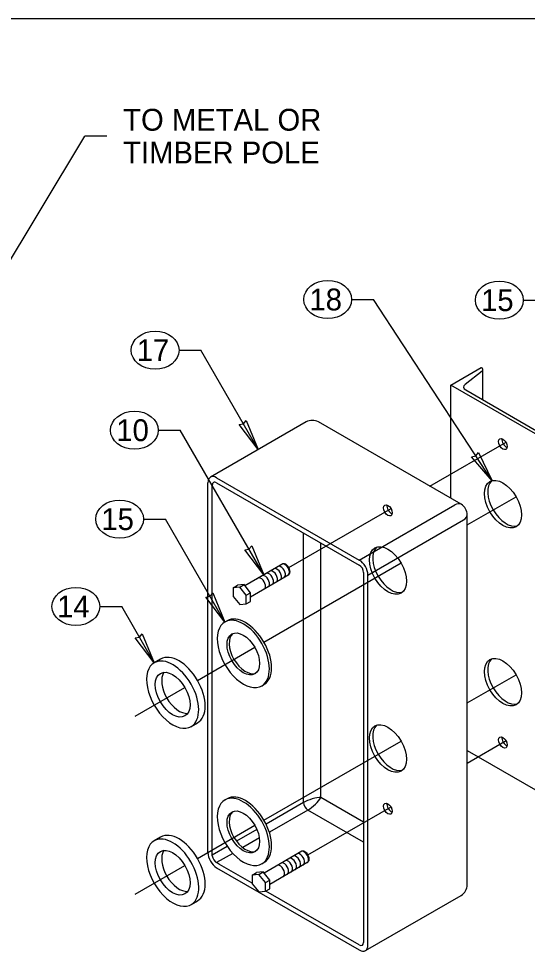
# Model space of a CAD drawing. Extents: x 99862 to 104211, y 98939 to 102076.
# Drawn here: x 101922 to 102294, y 101389 to 102076 of the extents above; entities that cross this region are included whole.
import ezdxf

# ---------------------------------------------------------------- set-up
doc = ezdxf.new("R2010")
doc.units = 0
for name, color, linetype in [('Level 1', 7, 'Continuous'), ('Level 13', 7, 'Continuous'), ('Level 14', 7, 'Continuous'), ('Level 15', 7, 'Continuous'), ('Level 17', 7, 'Continuous'), ('Level 19', 7, 'Continuous'), ('Level 20', 7, 'Continuous'), ('Level 37', 7, 'Continuous')]:
    doc.layers.add(name, color=color, linetype=linetype)

msp = doc.modelspace()

# ---------------------------------------------------------------- linework, layer by layer
at = {"layer": 'Level 1'}
msp.add_lwpolyline([(99862, 99999.5), (103151, 99999.5), (103151, 102075.5), (99862, 102075.5)], close=True, dxfattribs=at)
for centre in [(102116.86, 101671.77), (102105.16, 101665.01), (102108.08, 101666.7), (102111.01, 101668.39), (102113.93, 101670.08), (102099.31, 101661.64), (102102.23, 101663.33), (102127.93, 101459.54), (102130.85, 101461.23), (102113.31, 101451.1), (102116.23, 101452.79), (102119.15, 101454.48), (102122.08, 101456.17), (102125, 101457.85)]:
    msp.add_ellipse(centre, major_axis=(-2.33, 4.04), ratio=0.57735, start_param=2.878526, end_param=6.548134, dxfattribs=at)
at = {"layer": 'Level 13'}
for p, q in [((102132.38, 101780.05), (102062.38, 101739.63)), ((102245.77, 101719.78), (102141.38, 101780.05)), ((102066.88, 101739.19), (102171.27, 101678.92)), ((102060.52, 101467.64), (102060.52, 101735.51)), ((102063.7, 101462.25), (102063.7, 101733.68)), ((102066.88, 101735.51), (102171.27, 101675.25)), ((102171.27, 101678.92), (102241.27, 101719.34)), ((102250.27, 101440.99), (102250.27, 101711.99)), ((102177.63, 101667.9), (102247.63, 101708.31)), ((102130.52, 101501.26), (102130.52, 101698.77)), ((102143.25, 101504.94), (102143.25, 101691.42)), ((102174.45, 101669.73), (102174.45, 101398.74)), ((102177.63, 101396.9), (102177.63, 101667.9)), ((102174.45, 101486.92), (102143.25, 101504.93)), ((102130.52, 101501.26), (102103.08, 101485.42)), ((102133.7, 101495.75), (102105.46, 101479.44)), ((102174.45, 101472.22), (102133.7, 101495.75)), ((102096.36, 101481.54), (102081.42, 101472.91)), ((102098.17, 101475.24), (102085.97, 101468.19)), ((102060.52, 101464.52), (102060.52, 101467.64)), ((102074.7, 101469.03), (102063.7, 101462.68)), ((102078.68, 101463.98), (102066.88, 101457.17)), ((102069.03, 101455.93), (102066.88, 101457.17)), ((102092.99, 101442.09), (102069.03, 101455.93)), ((102066.88, 101453.49), (102171.27, 101393.23)), ((102171.27, 101396.9), (102102.88, 101436.38)), ((102175.77, 101392.78), (102245.77, 101433.2))]:
    msp.add_line(p, q, dxfattribs=at)
for centre, start, end in [((102136.88, 101772.26), 60, 120), ((102241.27, 101711.99), 360, 60), ((102241.27, 101440.99), 300, 360)]:
    msp.add_arc(centre, 9, start, end, dxfattribs=at)
for centre, major_axis, ratio, start_param, end_param in [((102066.88, 101731.84), (4.5, -7.79), 0.57735, 2.356194, 3.926991), ((102066.88, 101731.84), (2.25, -3.9), 0.57735, 2.356194, 3.926991), ((102194.65, 101716.68), (-2.25, 3.9), 0.57735, 0.55899, 2.582603), ((102241.27, 101711.99), (-4.5, -7.79), 0.57735, 3.141593, 3.926991), ((102241.27, 101711.99), (-9, 0), 0.57735, 2.356194, 3.141593), ((102194.65, 101672.58), (-9.56, 16.56), 0.57735, 0.12511, 3.016483), ((102171.27, 101671.57), (4.5, -7.79), 0.57735, 0.785398, 2.356194), ((102171.27, 101671.57), (2.25, -3.9), 0.57735, 0.785398, 2.356194), ((102194.65, 101542.15), (-9.56, 16.56), 0.57735, 0.12511, 3.016483), ((102136.88, 101501.26), (-8.97, -2.8), 0.264784, 3.844416, 5.415213), ((102136.88, 101501.26), (-6.91, -6.37), 0.264784, 0.867973, 2.438769), ((102133.7, 101499.42), (-2.25, 3.9), 0.57735, 0.785398, 2.356194), ((102194.65, 101498.06), (-2.25, 3.9), 0.57735, 0.55899, 2.582603), ((102066.88, 101460.84), (4.5, -7.79), 0.57735, 3.926991, 5.497787), ((102066.88, 101460.84), (2.25, -3.9), 0.57735, 4.04043, 5.497787), ((102171.27, 101400.57), (2.25, -3.9), 0.57735, 5.497787, 7.068583), ((102171.27, 101400.57), (4.5, -7.79), 0.57735, 5.497787, 7.068583)]:
    msp.add_ellipse(centre, major_axis=major_axis, ratio=ratio, start_param=start_param, end_param=end_param, dxfattribs=at)
for centre, major_axis in [((102192.26, 101715.3), (2.25, -3.9)), ((102192.26, 101671.21), (9.56, -16.56)), ((102192.26, 101540.77), (9.56, -16.56)), ((102192.26, 101496.68), (2.25, -3.9))]:
    msp.add_ellipse(centre, major_axis=major_axis, ratio=0.57735, dxfattribs=at)
at = {"layer": 'Level 14'}
for p, q in [((102025.89, 101606.33), (102021.2, 101603.63)), ((102048.2, 101556.86), (102052.89, 101559.57)), ((102025.89, 101475.9), (102021.2, 101473.19)), ((102048.2, 101426.43), (102052.89, 101429.13))]:
    msp.add_line(p, q, dxfattribs=at)
for centre, major_axis, start_param, end_param in [((102034.7, 101580.25), (-13.5, 23.38), 3.160814, 6.257875), ((102039.39, 101582.95), (-13.5, 23.38), 3.141593, 6.283185), ((102034.7, 101580.25), (-13.5, 23.38), 6.257875, 9.443999), ((102039.39, 101582.95), (9, -15.59), 3.404941, 4.712384), ((102039.39, 101582.95), (9, -15.59), 4.712384, 6.019837), ((102034.7, 101449.81), (-13.5, 23.38), 3.18937, 6.257397), ((102039.39, 101452.52), (-13.5, 23.38), 3.141593, 6.283185), ((102034.7, 101449.81), (-13.5, 23.38), 6.257397, 9.471744), ((102039.39, 101452.52), (9, -15.59), 3.404941, 4.712389), ((102039.39, 101452.52), (9, -15.59), 4.712389, 6.019837), ((102034.7, 101449.81), (-13.5, 23.38), 3.188559, 3.18937)]:
    msp.add_ellipse(centre, major_axis=major_axis, ratio=0.57735, start_param=start_param, end_param=end_param, dxfattribs=at)
for centre in [(102034.7, 101580.25), (102034.7, 101449.81)]:
    msp.add_ellipse(centre, major_axis=(9, -15.59), ratio=0.57735, dxfattribs=at)
at = {"layer": 'Level 15'}
for p, q in [((101891.9, 101858.89), (101970.48, 101989.49)), ((101986.48, 101989.49), (101970.48, 101989.49)), ((102165.69, 101869.79), (102181.69, 101869.79)), ((102268.46, 101737.02), (102181.69, 101869.79)), ((102291.28, 101869.3), (102307.28, 101869.3)), ((102039.35, 101832.65), (102055.35, 101832.65)), ((102097.38, 101759.84), (102055.35, 101832.65)), ((102024.22, 101774.02), (102040.22, 101774.02)), ((102101.4, 101668.04), (102040.22, 101774.02)), ((102222.9, 101732.99), (102278.67, 101765.19)), ((102250.27, 101704.7), (102285.99, 101725.32)), ((102119.72, 101673.42), (102194.51, 101716.6)), ((102013.39, 101708.87), (102029.39, 101708.87)), ((102072.92, 101633.48), (102029.39, 101708.87)), ((102101.51, 101618.81), (102201.82, 101676.73)), ((101981.39, 101644.87), (101997.39, 101644.87)), ((102021.2, 101603.63), (101997.39, 101644.87)), ((102052.89, 101590.74), (102094.86, 101614.97)), ((102250.27, 101574.27), (102285.99, 101594.89)), ((102007.35, 101564.45), (102043.7, 101585.44)), ((102101.51, 101488.38), (102201.82, 101546.29)), ((102250.27, 101530.17), (102278.67, 101546.57)), ((102133.71, 101462.88), (102194.51, 101497.98)), ((102052.89, 101460.31), (102094.86, 101484.54)), ((102007.35, 101434.01), (102043.7, 101455.01))]:
    msp.add_line(p, q, dxfattribs=at)
for points in [[(102097.38, 101759.84), (102083.38, 101778.12), (102086.5, 101778.7), (102088.55, 101781.11)], [(102268.46, 101737.02), (102253.47, 101754.5), (102256.55, 101755.24), (102258.47, 101757.76)], [(102101.4, 101668.04), (102087.41, 101686.32), (102090.52, 101686.9), (102092.57, 101689.3)], [(102072.92, 101633.48), (102058.92, 101651.76), (102062.03, 101652.34), (102064.09, 101654.75)], [(102021.2, 101603.63), (102007.2, 101621.91), (102010.32, 101622.48), (102012.37, 101624.89)]]:
    msp.add_lwpolyline(points, close=True, dxfattribs=at)
at = {"layer": 'Level 17'}
for p, q in [((102074.51, 101634.4), (102072.92, 101633.48)), ((102099.92, 101586.72), (102101.51, 101587.64)), ((102074.51, 101503.97), (102072.92, 101503.05)), ((102099.92, 101456.28), (102101.51, 101457.2))]:
    msp.add_line(p, q, dxfattribs=at)
for centre, major_axis, start_param, end_param in [((102086.42, 101610.1), (-13.5, 23.38), 3.156212, 6.257612), ((102088.01, 101611.02), (-13.5, 23.38), 3.141593, 6.283185), ((102086.42, 101610.1), (-13.5, 23.38), 6.263256, 9.438373), ((102088.01, 101611.02), (8.44, -14.61), 3.236014, 4.71245), ((102088.01, 101611.02), (8.44, -14.61), 4.71245, 6.188764), ((102086.42, 101479.67), (-13.5, 23.38), 3.161333, 6.262315), ((102088.01, 101480.59), (-13.5, 23.38), 3.141593, 6.283185), ((102086.42, 101479.67), (-13.5, 23.38), 6.262315, 9.444518), ((102088.01, 101480.59), (8.44, -14.61), 3.236014, 4.712389), ((102088.01, 101480.59), (8.44, -14.61), 4.712389, 6.188764)]:
    msp.add_ellipse(centre, major_axis=major_axis, ratio=0.57735, start_param=start_param, end_param=end_param, dxfattribs=at)
for centre in [(102086.42, 101610.1), (102086.42, 101479.67)]:
    msp.add_ellipse(centre, major_axis=(8.44, -14.61), ratio=0.57735, dxfattribs=at)
at = {"layer": 'Level 19'}
for p, q in [((102238.24, 101807.06), (102260.51, 101819.92)), ((102238.24, 101724.13), (102238.24, 101807.06)), ((102314.61, 101762.97), (102238.24, 101807.06)), ((102250.27, 101539.25), (102314.61, 101502.1))]:
    msp.add_line(p, q, dxfattribs=at)
for centre, major_axis in [((102276.42, 101763.89), (2.25, -3.9)), ((102276.42, 101719.8), (9.56, -16.56)), ((102276.42, 101589.37), (9.56, -16.56)), ((102276.42, 101545.27), (2.25, -3.9))]:
    msp.add_ellipse(centre, major_axis=major_axis, ratio=0.57735, dxfattribs=at)
at = {"layer": 'Level 20'}
for p, q in [((102260.51, 101819.92), (102260.82, 101819.74)), ((102261.14, 101817.2), (102248.67, 101807.58)), ((102261.81, 101796.21), (102261.81, 101818.37)), ((102249.17, 101803.51), (102308.45, 101769.28))]:
    msp.add_line(p, q, dxfattribs=at)
for centre in [(102148.19, 101869.79), (102273.78, 101869.3), (102021.85, 101832.65), (102006.72, 101774.02), (101995.89, 101708.87), (101963.89, 101644.87)]:
    msp.add_ellipse(centre, major_axis=(-17.5, 0), ratio=0.8, dxfattribs=at)
for centre, major_axis, start_param, end_param in [((102258.44, 101818.37), (3.38, 0), 5.640349, 7.068583), ((102252.99, 101805.71), (-5.4, 0), 5.640349, 7.068583), ((102278.81, 101765.27), (-2.25, 3.9), 0.55899, 2.582603), ((102278.81, 101721.18), (-9.56, 16.56), 0.12511, 3.016483), ((102278.81, 101590.74), (-9.56, 16.56), 0.12511, 3.016483), ((102278.81, 101546.65), (-2.25, 3.9), 0.55899, 2.582603)]:
    msp.add_ellipse(centre, major_axis=major_axis, ratio=0.57735, start_param=start_param, end_param=end_param, dxfattribs=at)
at = {"layer": 'Level 37'}
for p, q in [((102115.22, 101676.01), (102087.59, 101660.07)), ((102091.72, 101652.06), (102119.72, 101668.22)), ((102079, 101658.6), (102082.18, 101660.44)), ((102083.77, 101659.03), (102079, 101658.6)), ((102079, 101658.6), (102079, 101652.24)), ((102086.95, 101660.86), (102082.18, 101660.44)), ((102083.77, 101659.03), (102086.95, 101660.86)), ((102088.54, 101653.09), (102083.77, 101659.03)), ((102091.72, 101654.93), (102086.95, 101660.86)), ((102088.54, 101653.09), (102091.72, 101654.93)), ((102091.72, 101648.56), (102091.72, 101654.93)), ((102079, 101652.24), (102083.77, 101646.3)), ((102088.54, 101646.73), (102088.54, 101653.09)), ((102088.54, 101646.73), (102091.72, 101648.56)), ((102083.77, 101646.3), (102088.54, 101646.73)), ((102129.21, 101465.48), (102101.59, 101449.53)), ((102105.72, 101441.52), (102133.71, 101457.68)), ((102092.99, 101448.06), (102096.17, 101449.9)), ((102100.95, 101450.33), (102096.17, 101449.9)), ((102097.77, 101448.49), (102100.95, 101450.33)), ((102105.72, 101444.39), (102100.95, 101450.33)), ((102097.77, 101448.49), (102092.99, 101448.06)), ((102092.99, 101448.06), (102092.99, 101441.7)), ((102102.54, 101442.55), (102097.77, 101448.49)), ((102102.54, 101442.55), (102105.72, 101444.39)), ((102102.54, 101436.19), (102102.54, 101442.55)), ((102105.72, 101438.03), (102105.72, 101444.39)), ((102092.99, 101441.7), (102097.77, 101435.76)), ((102097.77, 101435.76), (102102.54, 101436.19)), ((102102.54, 101436.19), (102105.72, 101438.03))]:
    msp.add_line(p, q, dxfattribs=at)
for centre in [(102117.47, 101672.12), (102131.46, 101461.58)]:
    msp.add_ellipse(centre, major_axis=(2.25, -3.9), ratio=0.57735, start_param=6.28318, end_param=9.424778, dxfattribs=at)

# ---------------------------------------------------------------- texts
at = {"layer": 'Level 20'}
for s, p in [('TO METAL OR', (101998.48, 101993.49)), ('TIMBER POLE', (101998.48, 101969.49))]:
    msp.add_text(s, height=16, rotation=360, dxfattribs=at).set_placement(p)
for s, p in [('18', (102134.81, 101861.79)), ('15', (102260.4, 101861.3)), ('17', (102008.4, 101824.65)), ('10', (101993.46, 101766.02)), ('15', (101982.52, 101700.87)), ('14', (101950.11, 101636.87))]:
    msp.add_text(s, height=16, dxfattribs=at).set_placement(p)

doc.saveas('drawing.dxf')
